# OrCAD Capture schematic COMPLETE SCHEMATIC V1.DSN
size B; title: Item Tracking System; rev: C; note: Team1 SR GS AT MM
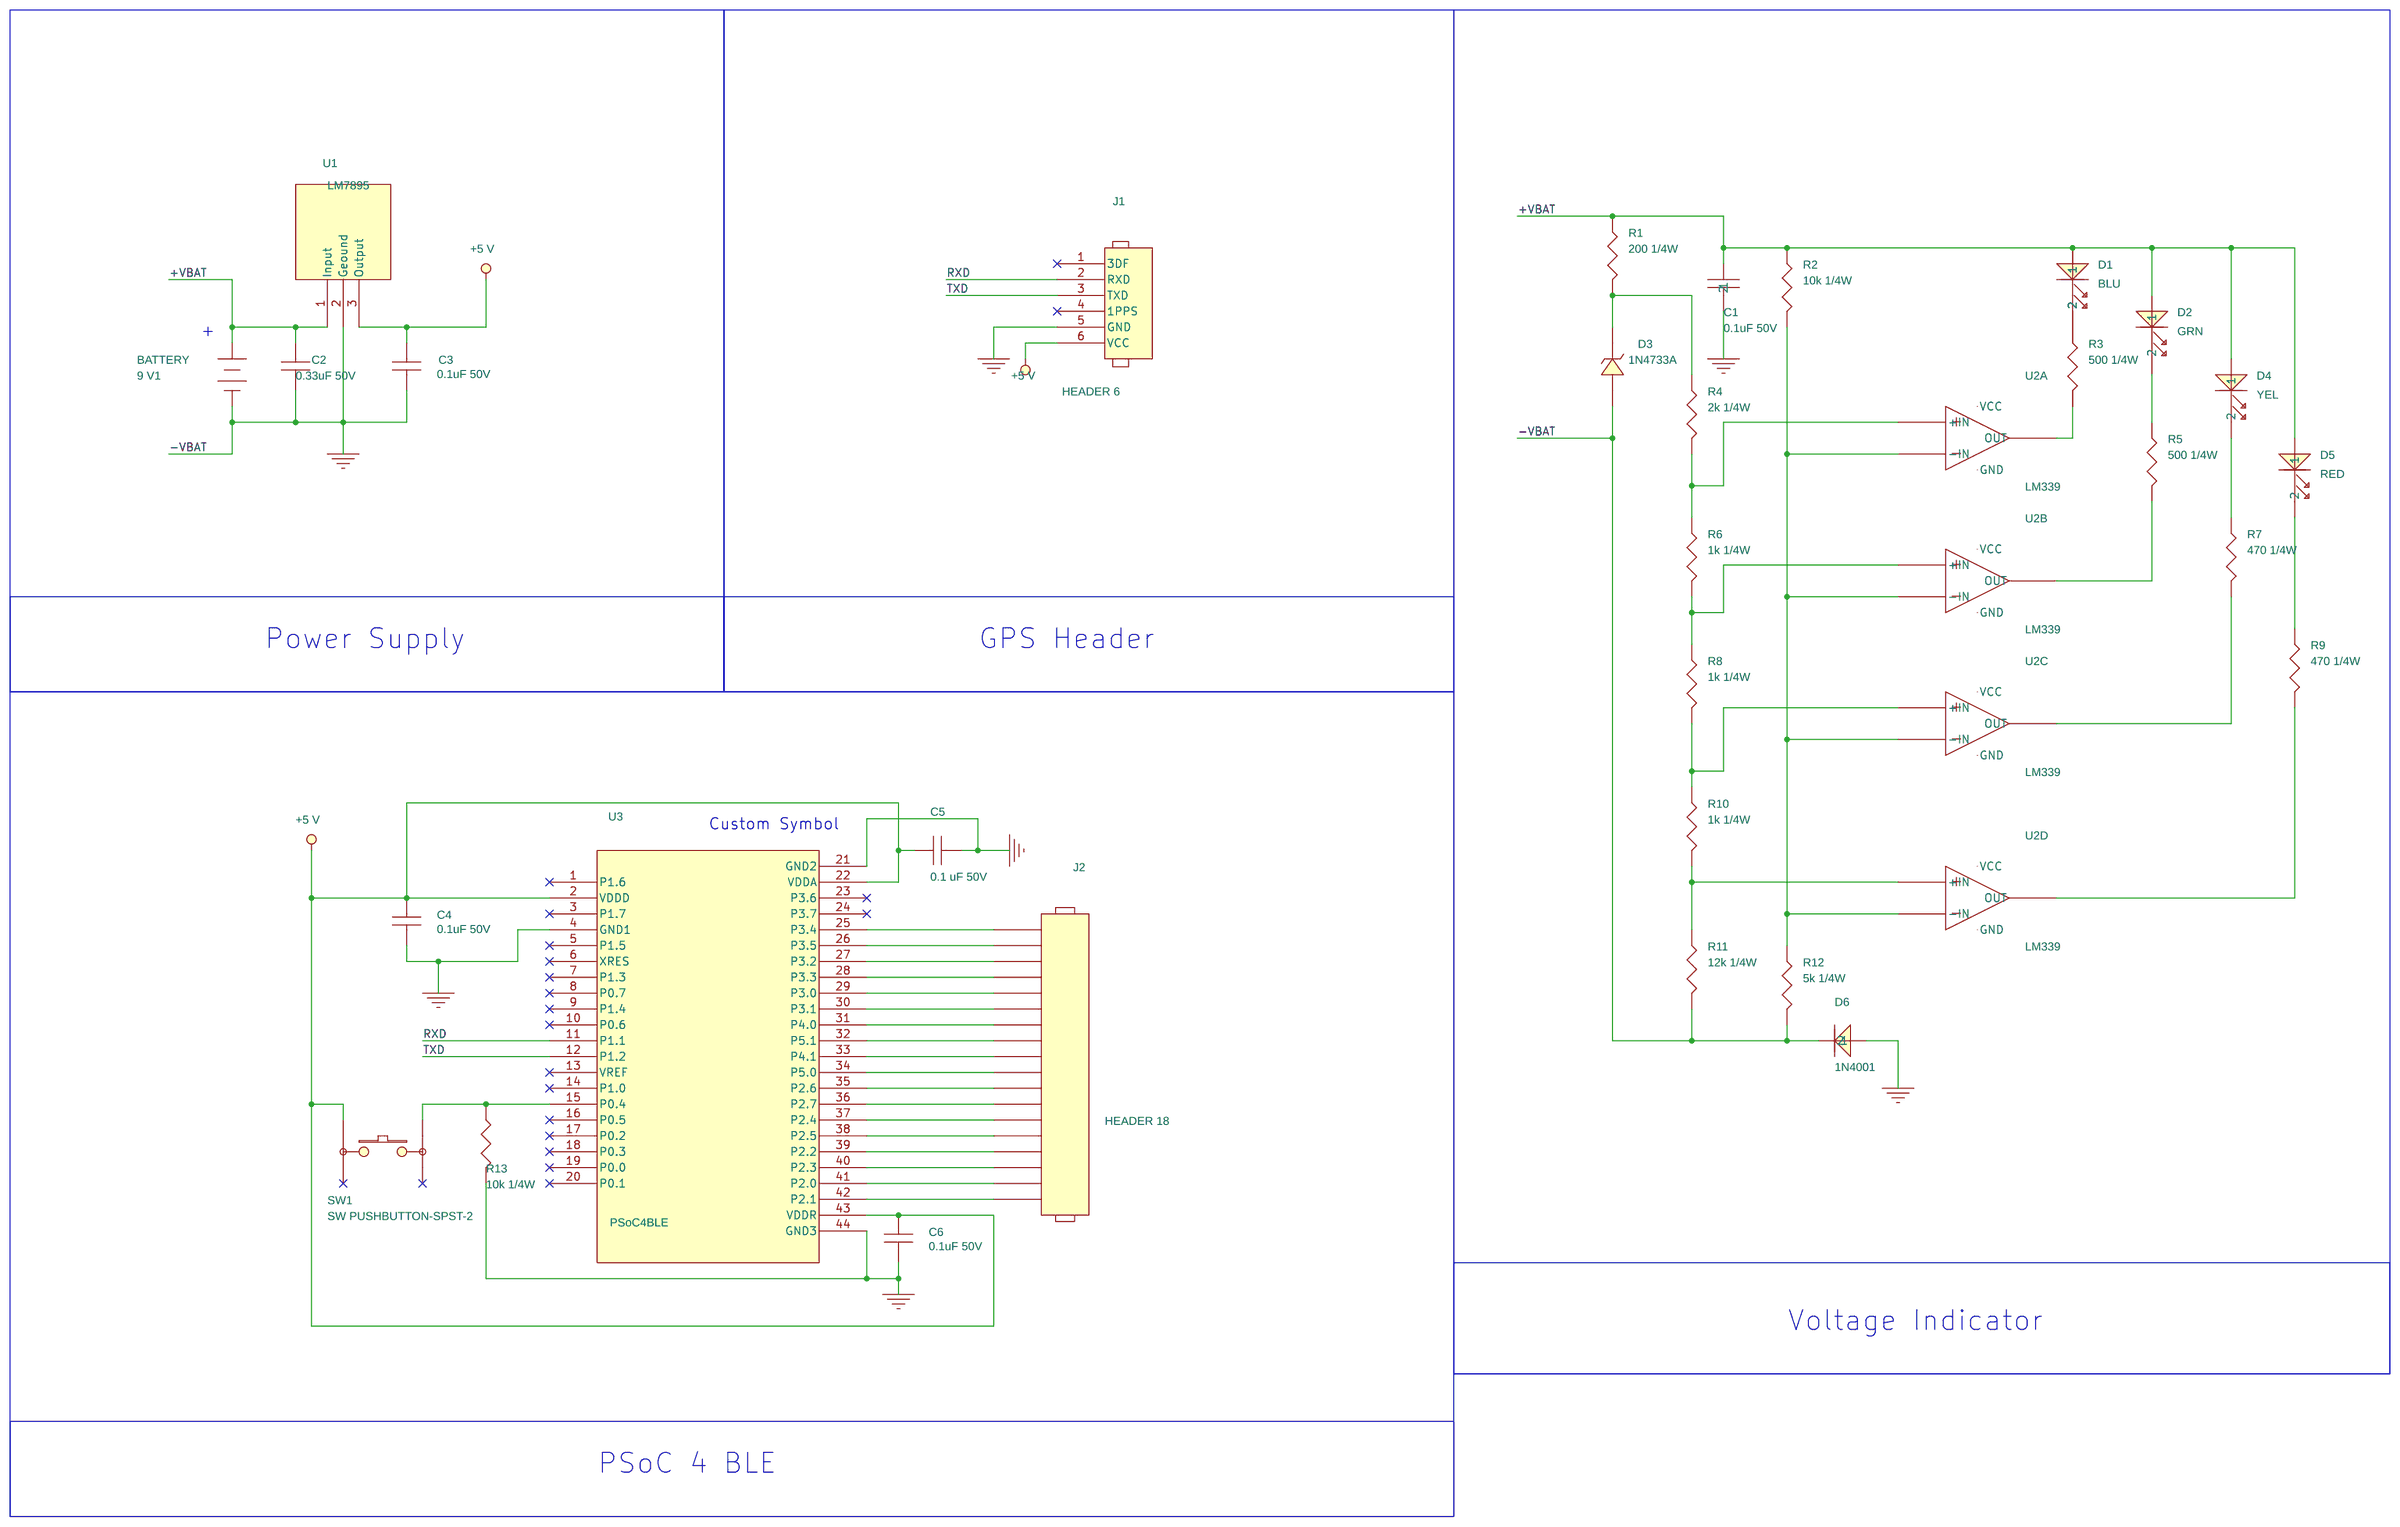
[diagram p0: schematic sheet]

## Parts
9 V1  BATTERY
C1  0.1uF 50V
C2  0.33uF 50V  [H2]
C3  0.1uF 50V  [H2]
C4  0.1uF 50V  [Cap1]
C5  0.1 uF 50V  [Cap1]
C6  0.1uF 50V  [Cap1]
D1  BLU
D2  GRN
D3  1N4733A
D4  YEL
D5  RED
D6  1N4001
J1  HEADER 6  [sip6]
J2  HEADER 18  [Header18]
R1  200 1/4W
R2  10k 1/4W
R3  500 1/4W
R4  2k 1/4W
R5  500 1/4W
R6  1k 1/4W
R7  470 1/4W
R8  1k 1/4W
R9  470 1/4W
R10  1k 1/4W
R11  12k 1/4W
R12  5k 1/4W
R13  10k 1/4W
SW1  SW PUSHBUTTON-SPST-2
U1  LM7895  [3]
U2  LM339  (sections A,B,C,D)
U3  PSoC4BLE  [PSOC4BLE]

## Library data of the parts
9 V1 = BATTERY
C1 = C
C2-C6 = CAP_NP
D1 = LED
D2 = LED_1
D3 = DIODE_ZENER
D4 = LED_2
D5 = LED_3
D6 = DIODE
J1 = HEADER_6_0
J2 = HEADER_18
R1 = R_5
R2 = R_3
R3 = R_2
R4 = R_4
R5 = R_11
R6 = R_8
R7 = R_9
R8 = R_7
R9 = R_12
R10 = R
R11 = R_10
R12 = R_1
R13 = R_6
SW1 = SW_PUSHBUTTON-SPST-2
U1 = Linear_regulator
U2 = LM339_1
U3 = PSoC4BLE_0

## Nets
+VBAT: 9 V1.1(+) C1.1 C2.1 D1.1 D2.1 D4.1 D5.1 R1.1 R2.1 U1.1(Input)
GND: 9 V1.2(-) C1.2 C2.2 C3.2 C4.2 C5.2 C6.2 D3.2(ANODE) D6.1 D6.2 J1.5(GND) R11.2 R12.2 R13.2 U1.2(Geound) U2.12(GND) U3.4(GND1) U3.21(GND2) U3.44(GND3)
VCC: U2.3(VCC)
+5 V: C3.1 C4.1 C5.1 C6.1 J1.6(VCC) SW1.1 U1.3(Output) U3.2(VDDD) U3.22(VDDA) U3.43(VDDR)
RXD: J1.2(RXD) U3.11(P1.1)
TXD: J1.3(TXD) U3.12(P1.2)
N56194: R3.2 U2.1(OUT)
N56202: R5.2 U2.2(OUT)
N56210: R7.2 U2.14(OUT)
N56218: R9.2 U2.13(OUT)
N56230: D3.1(CATHODE) R1.2 R4.1
N56234: R4.2 R6.1 U2.7(+IN)
N56238: R6.2 R8.1 U2.5(+IN)
N56242: R8.2 R10.1 U2.9(+IN)
N56246: R2.2 R12.1 U2.4(-IN) U2.6(-IN) U2.8(-IN) U2.10(-IN)
N56362: R10.2 R11.1 U2.11(+IN)
N56366: D2.2 R5.1
N56370: D4.2 R7.1
N56374: D5.2 R9.1
N56894: R13.1 SW1.4 U3.15(P0.4)
N57246: J2.18 U3.42(P2.1)
N57250: J2.17 U3.41(P2.0)
N57254: J2.16 U3.40(P2.3)
N57258: J2.15 U3.39(P2.2)
N57262: J2.14 U3.38(P2.5)
N57266: J2.13 U3.37(P2.4)
N57270: J2.12 U3.36(P2.7)
N57274: J2.11 U3.35(P2.6)
N57278: J2.10 U3.34(P5.0)
N57282: J2.9 U3.33(P4.1)
N57286: J2.8 U3.32(P5.1)
N57290: J2.7 U3.31(P4.0)
N57294: J2.6 U3.30(P3.1)
N57298: J2.5 U3.29(P3.0)
N57318: J2.4 U3.28(P3.3)
N57322: J2.3 U3.27(P3.2)
N57332: J2.2 U3.26(P3.5)
N57336: J2.1 U3.25(P3.4)
N61743: D1.2 R3.1

Not connected (* = marked no-connect by the designer): J1 1(3DF)* 4(1PPS)*; SW1 2* 3*; U3 1(P1.6)* 3(P1.7)* 5(P1.5)* 6(XRES)* 7(P1.3)* 8(P0.7)* 9(P1.4)* 10(P0.6)* 13(VREF)* 14(P1.0)* 16(P0.5)* 17(P0.2)* 18(P0.3)* 19(P0.0)* 20(P0.1)* 23(P3.6)* 24(P3.7)*

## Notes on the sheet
- +
- Power Supply
- GPS Header
- Custom Symbol
- Voltage Indicator
- PSoC 4 BLE
